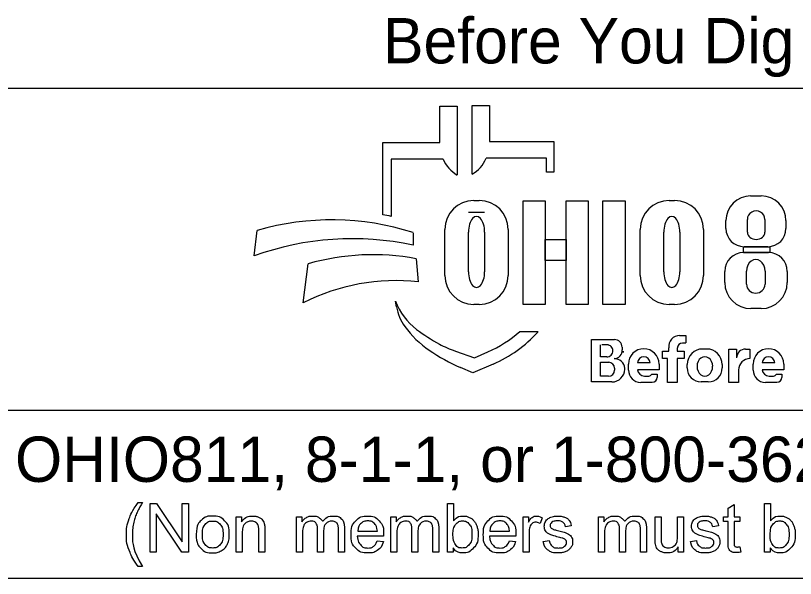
# Model space of a CAD drawing. Extents: x 0 to 34, y 0 to 22.
# Drawn here: x 2.424 to 4.831, y 2.143 to 3.88 of the extents above; entities that cross this region are included whole.
import ezdxf

# ---------------------------------------------------------------- set-up
doc = ezdxf.new("R2010")
doc.units = 0
doc.layers.add('SH_Data', color=7, linetype='Continuous')
doc.layers.add('SH_Text', color=7, linetype='Continuous')

msp = doc.modelspace()

# ---------------------------------------------------------------- linework, layer by layer
at = {"layer": 'SH_Data'}
for p, q in [((2.3775, 3.6553), (6.6275, 3.6553)), ((6.6275, 2.6607), (2.3775, 2.6607)), ((6.6275, 2.1428), (2.3775, 2.1428))]:
    msp.add_line(p, q, dxfattribs=at)
at = {"layer": 'SH_Text'}
for p, q in [((3.7335, 3.4883), (3.7335, 3.5998)), ((3.7335, 3.5998), (3.7872, 3.5998)), ((3.7872, 3.5998), (3.7872, 3.3877)), ((3.8329, 3.39), (3.8329, 3.6021)), ((3.8329, 3.6021), (3.8865, 3.6021)), ((3.8865, 3.6021), (3.8865, 3.4906)), ((3.5576, 3.2644), (3.5576, 3.4883)), ((3.5576, 3.4883), (3.7335, 3.4883)), ((3.8865, 3.4906), (4.0857, 3.4906)), ((4.0857, 3.4906), (4.0857, 3.3968)), ((3.5828, 3.4369), (3.5828, 3.26)), ((3.7439, 3.4369), (3.5828, 3.4369)), ((4.0625, 3.4392), (3.8761, 3.4392)), ((4.0625, 3.3968), (4.0625, 3.4392)), ((4.0857, 3.3968), (4.0625, 3.3968)), ((4.6931, 3.3231), (4.7258, 3.3231)), ((3.8385, 3.3091), (3.8551, 3.3091)), ((4.4416, 3.3091), (4.4581, 3.3091)), ((3.8718, 3.2721), (3.822, 3.2721)), ((4.683, 3.2111), (4.683, 3.2504)), ((4.7371, 3.2504), (4.7371, 3.2111)), ((4.6168, 3.2225), (4.6168, 3.2468)), ((4.8022, 3.2468), (4.8022, 3.2225)), ((3.1602, 3.1381), (3.1696, 3.2162)), ((3.6509, 3.2097), (3.6509, 3.1709)), ((3.7491, 3.0776), (3.7491, 3.2196)), ((3.822, 3.089), (3.822, 3.2114)), ((3.8718, 3.2114), (3.8718, 3.089)), ((3.9445, 3.2196), (3.9445, 3.0776)), ((4.3521, 3.0776), (4.3521, 3.2196)), ((4.425, 3.089), (4.425, 3.2114)), ((4.4748, 3.2114), (4.4748, 3.089)), ((4.5476, 3.2196), (4.5476, 3.0776)), ((4.7462, 3.1665), (4.6728, 3.1665)), ((4.671, 3.1482), (4.7483, 3.1482)), ((3.312, 2.9936), (3.3267, 3.1137)), ((3.6608, 3.1291), (3.6671, 3.0582)), ((4.6131, 3.0563), (4.6131, 3.0903)), ((4.6806, 3.0503), (4.6806, 3.0912)), ((4.7374, 3.0912), (4.7374, 3.0503)), ((4.8062, 3.0903), (4.8062, 3.0563)), ((3.5997, 2.9807), (3.5967, 2.9986)), ((3.8551, 2.9882), (3.8385, 2.9882)), ((4.4581, 2.9882), (4.4416, 2.9882)), ((4.7252, 2.9753), (4.6941, 2.9753)), ((3.98, 2.9048), (4.0375, 2.9048)), ((4.4739, 2.8926), (4.4934, 2.8926)), ((4.4934, 2.8926), (4.4934, 2.8696)), ((4.2013, 2.749), (4.2013, 2.8798)), ((4.2013, 2.8798), (4.2725, 2.8798)), ((4.4934, 2.8691), (4.4832, 2.8691)), ((3.7816, 2.8444), (3.841, 2.8239)), ((3.841, 2.8239), (3.8821, 2.8417)), ((4.2293, 2.8263), (4.2293, 2.8632)), ((4.2545, 2.8632), (4.2332, 2.8632)), ((4.2963, 2.856), (4.2963, 2.8481)), ((4.4213, 2.8212), (4.4213, 2.8442)), ((4.4213, 2.8442), (4.4406, 2.8442)), ((4.4406, 2.8442), (4.4406, 2.8546)), ((4.4667, 2.8526), (4.4667, 2.8442)), ((4.4667, 2.8442), (4.4883, 2.8442)), ((4.4883, 2.8442), (4.4883, 2.8212)), ((4.5451, 2.8508), (4.5573, 2.8508)), ((4.6254, 2.7478), (4.6254, 2.8505)), ((4.6254, 2.8505), (4.6499, 2.8505)), ((4.6499, 2.8505), (4.6499, 2.8237)), ((4.6772, 2.8505), (4.691, 2.8505)), ((4.691, 2.8505), (4.691, 2.8209)), ((4.2487, 2.8263), (4.2293, 2.8263)), ((4.4362, 2.8212), (4.4213, 2.8212)), ((4.4362, 2.7478), (4.4362, 2.8212)), ((4.4883, 2.8212), (4.4667, 2.8212)), ((4.4667, 2.8212), (4.4667, 2.7478)), ((3.835, 2.7769), (3.7976, 2.7934)), ((3.8983, 2.8044), (3.835, 2.7769)), ((4.2293, 2.7669), (4.2293, 2.8097)), ((4.2293, 2.8097), (4.2548, 2.8097)), ((4.3159, 2.7858), (4.3159, 2.8042)), ((4.3824, 2.8082), (4.3439, 2.8082)), ((4.4104, 2.8042), (4.4104, 2.7866)), ((4.4973, 2.7922), (4.4973, 2.8029)), ((4.6051, 2.8029), (4.6051, 2.7922)), ((4.7008, 2.7858), (4.7008, 2.8042)), ((4.7674, 2.8082), (4.7288, 2.8082)), ((4.7953, 2.8042), (4.7953, 2.7866)), ((4.2729, 2.7916), (4.2729, 2.7853)), ((4.3043, 2.7887), (4.3043, 2.7884)), ((4.4104, 2.7866), (4.344, 2.7866)), ((4.3876, 2.7729), (4.4045, 2.7729)), ((4.4045, 2.7729), (4.4045, 2.7631)), ((4.6559, 2.786), (4.6559, 2.7478)), ((4.7953, 2.7866), (4.7289, 2.7866)), ((4.7725, 2.7729), (4.7894, 2.7729)), ((4.7894, 2.7729), (4.7894, 2.7631)), ((4.265, 2.749), (4.2013, 2.749)), ((4.2546, 2.7669), (4.2293, 2.7669)), ((4.3892, 2.7478), (4.3538, 2.7478)), ((4.3649, 2.7673), (4.379, 2.7673)), ((4.4667, 2.7478), (4.4362, 2.7478)), ((4.5623, 2.7494), (4.5401, 2.7494)), ((4.6559, 2.7478), (4.6254, 2.7478)), ((4.7742, 2.7478), (4.7388, 2.7478)), ((4.7498, 2.7673), (4.7639, 2.7673))]:
    msp.add_line(p, q, dxfattribs=at)
for points in [[(3.991, 3.3081), (4.0589, 3.3081), (4.0589, 2.9881), (3.991, 2.9881)], [(4.1231, 3.3081), (4.1911, 3.3081), (4.1911, 2.9881), (4.1231, 2.9881)], [(4.2364, 3.3081), (4.3052, 3.3081), (4.3052, 2.9881), (4.2364, 2.9881)], [(4.0589, 3.1882), (4.1231, 3.1882), (4.1231, 3.1242), (4.0589, 3.1242)], [(4.6706, 3.1665), (4.7523, 3.1665), (4.7523, 3.1481), (4.6706, 3.1481)]]:
    msp.add_lwpolyline(points, close=True, dxfattribs=at)
for points in [[(2.8021, 2.3766), (2.8153, 2.3766)], [(2.8389, 2.2239), (2.8389, 2.3741), (2.8592, 2.3741), (2.9382, 2.2561), (2.9382, 2.3741), (2.9572, 2.3741), (2.9572, 2.2239), (2.9369, 2.2239), (2.8579, 2.3419), (2.8579, 2.2239), (2.8389, 2.2239)], [(3.7743, 2.2239), (3.7573, 2.2239), (3.7573, 2.3741), (3.7757, 2.3741), (3.7757, 2.3206)], [(4.6233, 2.2558), (4.6233, 2.3185), (4.6097, 2.3185), (4.6097, 2.3328), (4.6233, 2.3328), (4.6233, 2.3597), (4.6417, 2.3708), (4.6417, 2.3328), (4.6601, 2.3328), (4.6601, 2.3185), (4.6417, 2.3185), (4.6417, 2.2547)], [(4.7534, 2.2239), (4.7363, 2.2239), (4.7363, 2.3741), (4.7548, 2.3741), (4.7548, 2.3206)], [(3.1048, 2.2239), (3.1048, 2.3328), (3.1214, 2.3328), (3.1214, 2.3173)], [(3.2912, 2.2239), (3.2912, 2.3328), (3.3077, 2.3328), (3.3077, 2.3174)], [(3.5826, 2.2239), (3.5826, 2.3328), (3.5991, 2.3328), (3.5991, 2.3174)], [(3.9904, 2.2239), (3.9904, 2.3328), (4.007, 2.3328), (4.007, 2.3163)], [(4.0495, 2.3293), (4.043, 2.3122)], [(4.2236, 2.2239), (4.2236, 2.3328), (4.2401, 2.3328), (4.2401, 2.3174)], [(4.3979, 2.2654), (4.3979, 2.3328), (4.4164, 2.3328), (4.4164, 2.2724)], [(4.4676, 2.2745), (4.4676, 2.3328), (4.4861, 2.3328), (4.4861, 2.2239), (4.4696, 2.2239)], [(3.1932, 2.2908), (3.1932, 2.2239), (3.1748, 2.2239), (3.1748, 2.2901)], [(3.3743, 2.2871), (3.3743, 2.2239), (3.3559, 2.2239), (3.3559, 2.2946)], [(3.4388, 2.2986), (3.4388, 2.2239), (3.4203, 2.2239), (3.4203, 2.2924)], [(3.4799, 2.2887), (3.5406, 2.2887)], [(3.6657, 2.2871), (3.6657, 2.2239), (3.6473, 2.2239), (3.6473, 2.2946)], [(3.7301, 2.2986), (3.7301, 2.2239), (3.7117, 2.2239), (3.7117, 2.2924)], [(3.8879, 2.2887), (3.9486, 2.2887)], [(4.1394, 2.3046), (4.1213, 2.3022)], [(4.3067, 2.2871), (4.3067, 2.2239), (4.2883, 2.2239), (4.2883, 2.2946)], [(4.3711, 2.2986), (4.3711, 2.2239), (4.3527, 2.2239), (4.3527, 2.2924)], [(4.594, 2.3046), (4.5759, 2.3022)], [(3.1233, 2.2833), (3.1233, 2.2239), (3.1048, 2.2239)], [(3.3097, 2.2803), (3.3097, 2.2239), (3.2912, 2.2239)], [(3.56, 2.2736), (3.4788, 2.2736)], [(3.601, 2.2803), (3.601, 2.2239), (3.5826, 2.2239)], [(3.968, 2.2736), (3.8868, 2.2736)], [(4.0088, 2.2809), (4.0088, 2.2239), (3.9904, 2.2239)], [(4.242, 2.2803), (4.242, 2.2239), (4.2236, 2.2239)], [(3.5404, 2.2591), (3.5595, 2.2567)], [(3.9484, 2.2591), (3.9675, 2.2567)], [(4.053, 2.2564), (4.0712, 2.2593)], [(4.4696, 2.2239), (4.4696, 2.24)], [(4.5076, 2.2564), (4.5258, 2.2593)], [(4.6601, 2.2404), (4.6628, 2.2241)], [(3.7743, 2.2375), (3.7743, 2.2239)], [(4.7534, 2.2375), (4.7534, 2.2239)], [(2.8153, 2.1798), (2.8021, 2.1798)]]:
    msp.add_lwpolyline(points, dxfattribs=at)
for centre, radius, start, end in [((3.8353, 3.4736), 0.0985, 201.9296, 240.7469), ((3.7847, 3.476), 0.0985, 299.2531, 338.0704), ((4.6931, 3.2468), 0.0763, 90, 180), ((4.7258, 3.2468), 0.0763, 0, 90), ((3.8385, 3.2196), 0.0895, 90, 180), ((3.8551, 3.2196), 0.0895, 0, 90), ((4.4416, 3.2196), 0.0895, 90, 180), ((4.4581, 3.2196), 0.0895, 0, 90), ((3.4295, 2.4554), 0.8191, 79.2074, 81.0007), ((3.3997, 2.4302), 0.8191, 72.1402, 106.3144), ((4.6728, 3.2225), 0.056, 180, 270), ((4.7462, 3.2225), 0.056, 270, 0), ((3.4628, 2.2991), 0.8919, 77.8238, 109.8274), ((3.5267, 2.4094), 0.7322, 79.44, 105.8467), ((4.671, 3.0903), 0.0579, 90, 180), ((4.7483, 3.0903), 0.0579, 0, 90), ((3.5987, 2.4262), 0.6357, 83.8248, 116.8021), ((3.8385, 3.0776), 0.0895, 180, 270), ((3.8551, 3.0776), 0.0895, 270, 0), ((4.4416, 3.0776), 0.0895, 180, 270), ((4.4581, 3.0776), 0.0895, 270, 0), ((4.6941, 3.0563), 0.081, 180, 270), ((4.7252, 3.0563), 0.081, 270, 0), ((3.7841, 3.0707), 0.2008, 201.0457, 232.5314), ((3.741, 3.0048), 0.1433, 189.6817, 216.0884), ((3.8747, 3.1022), 0.3088, 216.0884, 235.7167), ((3.9766, 3.3219), 0.5173, 232.5314, 241.794), ((3.7387, 3.1722), 0.3602, 293.4582, 312.0712), ((3.7387, 3.1722), 0.401, 293.4582, 317.8286), ((4.4739, 2.859), 0.0335, 90, 187.5187), ((3.8914, 3.1631), 0.3371, 241.794, 250.9821), ((4.2725, 2.856), 0.0238, 0, 90), ((4.4832, 2.8526), 0.0165, 90, 180), ((4.0412, 3.3465), 0.6044, 235.7167, 246.2325), ((4.2487, 2.845), 0.0187, 270, 2.0582), ((4.2505, 2.8463), 0.0169, 357.8325, 90), ((4.2721, 2.8453), 0.0243, 270, 6.6529), ((4.2827, 2.8438), 0.0175, 347.4023, 0), ((4.3631, 2.8042), 0.0473, 0, 180), ((4.5451, 2.8029), 0.0478, 90, 180), ((4.5573, 2.8029), 0.0478, 0, 90), ((4.6768, 2.8237), 0.0269, 89.2449, 180), ((4.7481, 2.8042), 0.0473, 0, 180), ((4.2722, 2.7889), 0.0321, 4.0748, 90), ((4.3632, 2.8072), 0.0193, 2.9632, 177.0368), ((4.6908, 2.786), 0.0349, 89.6033, 180), ((4.7481, 2.8072), 0.0193, 2.9632, 177.0368), ((4.2548, 2.7916), 0.0181, 0, 90), ((4.2714, 2.7887), 0.033, 0, 11.7502), ((4.2546, 2.7853), 0.0184, 270, 0), ((4.265, 2.7884), 0.0393, 270, 0), ((4.3538, 2.7858), 0.038, 180, 270), ((4.3649, 2.7883), 0.021, 184.827, 270), ((4.379, 2.7767), 0.00938, 270, 335.9979), ((4.5401, 2.7922), 0.0428, 180, 270), ((4.5623, 2.7922), 0.0428, 270, 0), ((4.7388, 2.7858), 0.038, 180, 270), ((4.7498, 2.7883), 0.021, 184.827, 270), ((4.7639, 2.7767), 0.00938, 270, 335.9979), ((4.3892, 2.7631), 0.0152, 270, 0), ((4.7742, 2.7631), 0.0152, 270, 0)]:
    msp.add_arc(centre, radius, start, end, dxfattribs=at)
for centre, major_axis, ratio, start_param, end_param in [((4.71, 3.2504), (0.0271, 0), 0.969373, 0, 3.141593), ((3.8469, 3.2114), (0, 0.0484), 0.514403, 4.712389, 7.853982), ((4.4499, 3.2114), (0, 0.0484), 0.514403, 4.712389, 7.853982), ((4.71, 3.2111), (0.0271, 0), 0.818453, 3.141593, 6.283185), ((4.709, 3.0912), (0, 0.0358), 0.794529, 4.712389, 7.853982), ((3.8469, 3.089), (0, 0.0484), 0.514403, 1.570796, 4.712389), ((4.4499, 3.089), (0, 0.0484), 0.514403, 1.570796, 4.712389), ((4.709, 3.0503), (0.0284, 0), 0.959837, 3.141593, 6.283185), ((4.5517, 2.7976), (0, 0.029), 0.832186, 4.712389, 7.853982), ((4.5517, 2.7976), (0, 0.0302), 0.797287, 1.570796, 4.712389)]:
    msp.add_ellipse(centre, major_axis=major_axis, ratio=ratio, start_param=start_param, end_param=end_param, dxfattribs=at)
for points in [[(2.8021, 2.1798), (2.7869, 2.199), (2.7763, 2.2248), (2.7657, 2.2506), (2.7657, 2.2783), (2.7657, 2.3026), (2.7736, 2.325), (2.7829, 2.3509), (2.8021, 2.3766)], [(2.8153, 2.3766), (2.8029, 2.3553), (2.7989, 2.3462), (2.7927, 2.332), (2.7891, 2.3167), (2.7847, 2.2975), (2.7847, 2.2782), (2.7847, 2.2289), (2.8153, 2.1798)], [(2.9814, 2.2783), (2.9814, 2.3085), (2.9981, 2.3231), (3.0122, 2.3352), (3.0323, 2.3352), (3.0547, 2.3352), (3.069, 2.3205), (3.0832, 2.3058), (3.0832, 2.2799), (3.0832, 2.2589), (3.0769, 2.2469), (3.0706, 2.2348), (3.0586, 2.2282), (3.0466, 2.2215), (3.0323, 2.2215), (3.0095, 2.2215), (2.9954, 2.2362), (2.9814, 2.2508), (2.9814, 2.2783)], [(3.0003, 2.2783), (3.0003, 2.2574), (3.0094, 2.247), (3.0185, 2.2366), (3.0323, 2.2366), (3.046, 2.2366), (3.0551, 2.2471), (3.0642, 2.2575), (3.0642, 2.279), (3.0642, 2.2991), (3.0551, 2.3095), (3.0459, 2.3199), (3.0323, 2.3199), (3.0185, 2.3199), (3.0094, 2.3096), (3.0003, 2.2992), (3.0003, 2.2783)], [(3.1214, 2.3173), (3.1334, 2.3352), (3.156, 2.3352), (3.1659, 2.3352), (3.1741, 2.3316), (3.1823, 2.3281), (3.1864, 2.3224), (3.1905, 2.3166), (3.1922, 2.3087), (3.1932, 2.3036), (3.1932, 2.2908)], [(3.1748, 2.2901), (3.1748, 2.3013), (3.1726, 2.3069), (3.1705, 2.3125), (3.165, 2.3158), (3.1595, 2.3191), (3.1521, 2.3191), (3.1404, 2.3191), (3.1318, 2.3117), (3.1233, 2.3042), (3.1233, 2.2833)], [(3.3077, 2.3174), (3.3128, 2.3254), (3.3214, 2.3303), (3.3299, 2.3352), (3.3407, 2.3352), (3.3528, 2.3352), (3.3606, 2.3301), (3.3683, 2.3251), (3.3715, 2.3161), (3.3844, 2.3352), (3.4051, 2.3352), (3.4213, 2.3352), (3.43, 2.3262), (3.4388, 2.3172), (3.4388, 2.2986)], [(3.3559, 2.2946), (3.3559, 2.3069), (3.3514, 2.313), (3.3469, 2.3191), (3.3366, 2.3191), (3.3288, 2.3191), (3.3222, 2.315), (3.3156, 2.311), (3.3126, 2.3031), (3.3097, 2.2952), (3.3097, 2.2803)], [(3.4203, 2.2924), (3.4203, 2.3035), (3.4185, 2.3083), (3.4168, 2.3132), (3.412, 2.3162), (3.4073, 2.3191), (3.401, 2.3191), (3.3895, 2.3191), (3.3819, 2.3115), (3.3743, 2.3039), (3.3743, 2.2871)], [(3.5595, 2.2567), (3.555, 2.24), (3.5428, 2.2307), (3.5306, 2.2215), (3.5117, 2.2215), (3.4878, 2.2215), (3.4738, 2.2362), (3.4598, 2.2509), (3.4598, 2.2774), (3.4598, 2.3049), (3.474, 2.32), (3.4881, 2.3352), (3.5106, 2.3352), (3.5324, 2.3352), (3.5463, 2.3203), (3.5601, 2.3055), (3.5601, 2.2785), (3.5601, 2.2769), (3.56, 2.2736)], [(3.5406, 2.2887), (3.5394, 2.3025), (3.5337, 2.3094), (3.5249, 2.3201), (3.5108, 2.3201), (3.4981, 2.3201), (3.4894, 2.3115), (3.4808, 2.303), (3.4799, 2.2887)], [(3.5991, 2.3174), (3.6042, 2.3254), (3.6127, 2.3303), (3.6212, 2.3352), (3.6321, 2.3352), (3.6442, 2.3352), (3.6519, 2.3301), (3.6597, 2.3251), (3.6628, 2.3161), (3.6758, 2.3352), (3.6965, 2.3352), (3.7127, 2.3352), (3.7214, 2.3262), (3.7301, 2.3172), (3.7301, 2.2986)], [(3.6473, 2.2946), (3.6473, 2.3069), (3.6428, 2.313), (3.6383, 2.3191), (3.628, 2.3191), (3.6202, 2.3191), (3.6136, 2.315), (3.607, 2.311), (3.604, 2.3031), (3.601, 2.2952), (3.601, 2.2803)], [(3.7117, 2.2924), (3.7117, 2.3035), (3.7099, 2.3083), (3.7081, 2.3132), (3.7034, 2.3162), (3.6987, 2.3191), (3.6923, 2.3191), (3.6809, 2.3191), (3.6733, 2.3115), (3.6657, 2.3039), (3.6657, 2.2871)], [(3.7741, 2.2792), (3.7741, 2.2596), (3.7794, 2.2509), (3.7881, 2.2366), (3.8029, 2.2366), (3.815, 2.2366), (3.8238, 2.2471), (3.8326, 2.2576), (3.8326, 2.2784), (3.8326, 2.2998), (3.8241, 2.3099), (3.8157, 2.3201), (3.8038, 2.3201), (3.7917, 2.3201), (3.7829, 2.3096), (3.7741, 2.299), (3.7741, 2.2792)], [(3.7757, 2.3206), (3.7874, 2.3352), (3.8055, 2.3352), (3.8155, 2.3352), (3.8245, 2.3311), (3.8335, 2.3271), (3.8392, 2.3198), (3.845, 2.3124), (3.8483, 2.3021), (3.8516, 2.2918), (3.8516, 2.28), (3.8516, 2.252), (3.8378, 2.2368), (3.8239, 2.2215), (3.8046, 2.2215), (3.7853, 2.2215), (3.7743, 2.2375)], [(3.9675, 2.2567), (3.963, 2.24), (3.9508, 2.2307), (3.9386, 2.2215), (3.9196, 2.2215), (3.8958, 2.2215), (3.8818, 2.2362), (3.8678, 2.2509), (3.8678, 2.2774), (3.8678, 2.3049), (3.882, 2.32), (3.8961, 2.3352), (3.9186, 2.3352), (3.9404, 2.3352), (3.9543, 2.3203), (3.9681, 2.3055), (3.9681, 2.2785), (3.9681, 2.2769), (3.968, 2.2736)], [(3.9486, 2.2887), (3.9474, 2.3025), (3.9417, 2.3094), (3.9328, 2.3201), (3.9188, 2.3201), (3.9061, 2.3201), (3.8974, 2.3115), (3.8888, 2.303), (3.8879, 2.2887)], [(4.007, 2.3163), (4.0133, 2.3278), (4.0187, 2.3315), (4.0241, 2.3352), (4.0305, 2.3352), (4.0398, 2.3352), (4.0495, 2.3293)], [(4.043, 2.3122), (4.0363, 2.3162), (4.0295, 2.3162), (4.0235, 2.3162), (4.0187, 2.3125), (4.0139, 2.3089), (4.0119, 2.3024), (4.0088, 2.2926), (4.0088, 2.2809)], [(4.1213, 2.3022), (4.1201, 2.3106), (4.1142, 2.3153), (4.1083, 2.3201), (4.0975, 2.3201), (4.0848, 2.3201), (4.0794, 2.3159), (4.0739, 2.3116), (4.0739, 2.306), (4.0739, 2.3024), (4.0762, 2.2995), (4.0785, 2.2966), (4.0833, 2.2946), (4.086, 2.2936), (4.0996, 2.2899), (4.1192, 2.2847), (4.1269, 2.2813), (4.1347, 2.278), (4.1391, 2.2717), (4.1435, 2.2653), (4.1435, 2.2559), (4.1435, 2.2467), (4.1381, 2.2386), (4.1327, 2.2304), (4.1226, 2.226), (4.1124, 2.2215), (4.0996, 2.2215), (4.0784, 2.2215), (4.0672, 2.2303), (4.0561, 2.2391), (4.053, 2.2564)], [(4.0712, 2.2593), (4.0727, 2.2483), (4.0798, 2.2425), (4.0868, 2.2366), (4.0995, 2.2366), (4.1122, 2.2366), (4.1184, 2.2418), (4.1245, 2.247), (4.1245, 2.254), (4.1245, 2.2602), (4.1191, 2.2638), (4.1153, 2.2663), (4.1002, 2.2701), (4.0799, 2.2752), (4.072, 2.2789), (4.0642, 2.2827), (4.0601, 2.2893), (4.0561, 2.2959), (4.0561, 2.3038), (4.0561, 2.3111), (4.0594, 2.3173), (4.0628, 2.3235), (4.0685, 2.3276), (4.0728, 2.3308), (4.0803, 2.333), (4.0877, 2.3352), (4.0962, 2.3352), (4.109, 2.3352), (4.1187, 2.3315), (4.1284, 2.3278), (4.133, 2.3215), (4.1377, 2.3152), (4.1394, 2.3046)], [(4.2401, 2.3174), (4.2452, 2.3254), (4.2537, 2.3303), (4.2622, 2.3352), (4.2731, 2.3352), (4.2852, 2.3352), (4.2929, 2.3301), (4.3007, 2.3251), (4.3038, 2.3161), (4.3168, 2.3352), (4.3375, 2.3352), (4.3537, 2.3352), (4.3624, 2.3262), (4.3711, 2.3172), (4.3711, 2.2986)], [(4.2883, 2.2946), (4.2883, 2.3069), (4.2838, 2.313), (4.2793, 2.3191), (4.269, 2.3191), (4.2612, 2.3191), (4.2546, 2.315), (4.248, 2.311), (4.245, 2.3031), (4.242, 2.2952), (4.242, 2.2803)], [(4.3527, 2.2924), (4.3527, 2.3035), (4.3509, 2.3083), (4.3491, 2.3132), (4.3444, 2.3162), (4.3397, 2.3191), (4.3333, 2.3191), (4.3219, 2.3191), (4.3143, 2.3115), (4.3067, 2.3039), (4.3067, 2.2871)], [(4.5759, 2.3022), (4.5747, 2.3106), (4.5688, 2.3153), (4.5629, 2.3201), (4.5521, 2.3201), (4.5394, 2.3201), (4.5339, 2.3159), (4.5285, 2.3116), (4.5285, 2.306), (4.5285, 2.3024), (4.5308, 2.2995), (4.533, 2.2966), (4.5378, 2.2946), (4.5406, 2.2936), (4.5542, 2.2899), (4.5737, 2.2847), (4.5815, 2.2813), (4.5893, 2.278), (4.5937, 2.2717), (4.5981, 2.2653), (4.5981, 2.2559), (4.5981, 2.2467), (4.5927, 2.2386), (4.5873, 2.2304), (4.5772, 2.226), (4.567, 2.2215), (4.5542, 2.2215), (4.5329, 2.2215), (4.5218, 2.2303), (4.5107, 2.2391), (4.5076, 2.2564)], [(4.5258, 2.2593), (4.5273, 2.2483), (4.5343, 2.2425), (4.5414, 2.2366), (4.554, 2.2366), (4.5668, 2.2366), (4.5729, 2.2418), (4.5791, 2.247), (4.5791, 2.254), (4.5791, 2.2602), (4.5736, 2.2638), (4.5698, 2.2663), (4.5548, 2.2701), (4.5345, 2.2752), (4.5266, 2.2789), (4.5188, 2.2827), (4.5147, 2.2893), (4.5107, 2.2959), (4.5107, 2.3038), (4.5107, 2.3111), (4.514, 2.3173), (4.5173, 2.3235), (4.5231, 2.3276), (4.5274, 2.3308), (4.5348, 2.333), (4.5423, 2.3352), (4.5508, 2.3352), (4.5636, 2.3352), (4.5733, 2.3315), (4.583, 2.3278), (4.5876, 2.3215), (4.5922, 2.3152), (4.594, 2.3046)], [(4.7532, 2.2792), (4.7532, 2.2596), (4.7585, 2.2509), (4.7672, 2.2366), (4.782, 2.2366), (4.7941, 2.2366), (4.8029, 2.2471), (4.8116, 2.2576), (4.8116, 2.2784), (4.8116, 2.2998), (4.8032, 2.3099), (4.7948, 2.3201), (4.7828, 2.3201), (4.7708, 2.3201), (4.762, 2.3096), (4.7532, 2.299), (4.7532, 2.2792)], [(4.7548, 2.3206), (4.7664, 2.3352), (4.7846, 2.3352), (4.7946, 2.3352), (4.8036, 2.3311), (4.8125, 2.3271), (4.8183, 2.3198), (4.8241, 2.3124), (4.8274, 2.3021), (4.8306, 2.2918), (4.8306, 2.28), (4.8306, 2.252), (4.8168, 2.2368), (4.803, 2.2215), (4.7836, 2.2215), (4.7644, 2.2215), (4.7534, 2.2375)], [(3.4788, 2.2736), (3.4799, 2.2557), (3.489, 2.2462), (3.4981, 2.2366), (3.5117, 2.2366), (3.5219, 2.2366), (3.5291, 2.242), (3.5362, 2.2473), (3.5404, 2.2591)], [(3.8868, 2.2736), (3.8879, 2.2557), (3.897, 2.2462), (3.9061, 2.2366), (3.9197, 2.2366), (3.9299, 2.2366), (3.937, 2.242), (3.9442, 2.2473), (3.9484, 2.2591)], [(4.4696, 2.24), (4.4569, 2.2215), (4.4351, 2.2215), (4.4255, 2.2215), (4.4171, 2.2252), (4.4088, 2.2289), (4.4047, 2.2345), (4.4007, 2.2401), (4.3991, 2.2482), (4.3979, 2.2536), (4.3979, 2.2654)], [(4.4164, 2.2724), (4.4164, 2.258), (4.4175, 2.253), (4.4192, 2.2457), (4.4249, 2.2416), (4.4305, 2.2374), (4.4388, 2.2374), (4.4471, 2.2374), (4.4543, 2.2417), (4.4616, 2.2459), (4.4646, 2.2533), (4.4676, 2.2606), (4.4676, 2.2745)], [(4.6628, 2.2241), (4.655, 2.2224), (4.6488, 2.2224), (4.6388, 2.2224), (4.6333, 2.2256), (4.6278, 2.2288), (4.6255, 2.234), (4.6233, 2.2392), (4.6233, 2.2558)], [(4.6417, 2.2547), (4.6417, 2.2468), (4.6427, 2.2445), (4.6436, 2.2423), (4.6458, 2.2409), (4.648, 2.2396), (4.6521, 2.2396), (4.6551, 2.2396), (4.6601, 2.2404)]]:
    msp.add_open_spline(points, degree=3, dxfattribs=at)

# ---------------------------------------------------------------- texts
for s, p in [('Before You Dig', (3.5583, 3.7321)), ('OHIO811, 8-1-1, or 1-800-362-2764', (2.422, 2.4406))]:
    msp.add_text(s, height=0.14, dxfattribs=at).set_placement(p)

doc.saveas('drawing.dxf')
